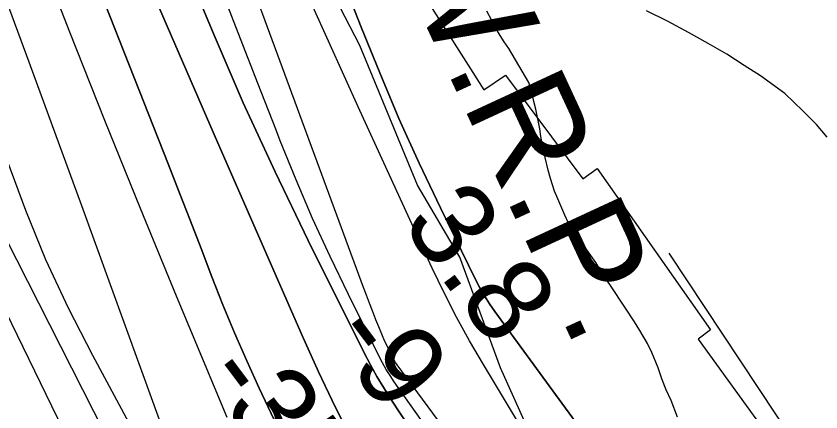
# Model space of a CAD drawing. Extents: x 3567028 to 3605064, y 510945 to 536587.
# Drawn here: x 3579101 to 3579738, y 530496 to 530809 of the extents above; entities that cross this region are included whole.
import ezdxf

# ---------------------------------------------------------------- set-up
doc = ezdxf.new("R2010")
doc.units = 0
for name, color, linetype in [('V-RIVR-EDGE', 7, 'Continuous'), ('V-RIVR-RANG', 7, 'Continuous'), ('V-RRAP-FSHR', 7, 'Continuous'), ('V-RRAP-RVMT', 7, 'Continuous'), ('V-SITE-VEGE', 7, 'Continuous'), ('V-TOPO-DPTH', 7, 'Continuous'), ('V-TOPO-MAJR', 7, 'Continuous'), ('V-TOPO-MINR', 7, 'Continuous'), ('V-TOPO-WATR', 7, 'Continuous'), ('V-TOPO-WATR-IDEN', 7, 'Continuous'), ('V-WETL-SWMP', 7, 'Continuous')]:
    doc.layers.add(name, color=color, linetype=linetype)

msp = doc.modelspace()

# ---------------------------------------------------------------- linework, layer by layer
at = {"layer": 'V-RIVR-EDGE'}
msp.add_lwpolyline([(3579514.72, 530462.65), (3579484.25, 530530.74), (3579451.99, 530618.44), (3579418.43, 530675.5), (3579372.75, 530785.91), (3579337.99, 530853.39), (3579300.26, 530958.26), (3579257.55, 531030.06), (3579223.39, 531093.25), (3579207.54, 531126.38), (3579192.44, 531212.2), (3579171.12, 531262.49)], dxfattribs=at)
at = {"layer": 'V-RRAP-FSHR'}
msp.add_lwpolyline([(3579617.49, 530621.66), (3579815.21, 530322.96), (3579894.56, 530194.06), (3579936.47, 530070.35), (3579998.06, 529936.51), (3580089.68, 529839.06), (3580197.58, 529749.51), (3580318.38, 529667.87), (3580467.84, 529591.15), (3580544.57, 529572.68), (3580671.85, 529512.09)], dxfattribs=at)
at = {"layer": 'V-RRAP-RVMT'}
for p, q in [((3579389.55, 530879.64), (3579470.85, 530750.98)), ((3579470.85, 530750.98), (3579488.26, 530762.49)), ((3579488.26, 530762.49), (3579549.35, 530680.51)), ((3579549.35, 530680.51), (3579560.62, 530688.63)), ((3579560.62, 530688.63), (3579650.29, 530561)), ((3579650.29, 530561), (3579640.58, 530553.51)), ((3579640.58, 530553.51), (3579812.75, 530316.3))]:
    msp.add_line(p, q, dxfattribs=at)
at = {"layer": 'V-SITE-VEGE'}
for points in [[(3579603.87, 530542.87), (3579600.56, 530550.07), (3579594.56, 530560.27), (3579590.35, 530567.16), (3579583.14, 530577.96), (3579570.83, 530596.84), (3579566.02, 530603.44), (3579559.72, 530614.23), (3579548.61, 530629.83), (3579544.4, 530635.22), (3579541.1, 530640.32), (3579538.1, 530645.42), (3579535.09, 530651.71), (3579529.68, 530664.61), (3579526.98, 530670.61), (3579523.67, 530680.8), (3579521.87, 530687.4), (3579519.46, 530697.3), (3579516.15, 530713.8), (3579515.24, 530720.09), (3579512.23, 530735.69), (3579510.43, 530741.69), (3579509.22, 530747.99), (3579506.52, 530756.69), (3579490.9, 530783.67), (3579486.99, 530788.77), (3579483.99, 530793.87), (3579479.79, 530801.06), (3579477.38, 530805.86), (3579473.48, 530813.06)], [(3579624.3, 530491.89), (3579619.19, 530505.09), (3579615.29, 530513.48), (3579611.98, 530522.18), (3579608.98, 530530.88), (3579603.87, 530542.87)]]:
    msp.add_lwpolyline(points, dxfattribs=at)
at = {"layer": 'V-TOPO-DPTH'}
for points in [[(3578940.6, 531474), (3579080.39, 531133.25), (3579124.43, 531026.96), (3579168.98, 530920.88), (3579214.27, 530815.11), (3579260.06, 530709.56), (3579327.19, 530556.31), (3579340.16, 530527.72), (3579353.64, 530499.38), (3579367.87, 530471.4)], [(3579367.87, 530471.4), (3579353.64, 530499.38), (3579340.16, 530527.72), (3579327.19, 530556.31), (3579260.06, 530709.56), (3579214.27, 530815.11), (3579168.98, 530920.88), (3579124.43, 531026.96), (3579080.39, 531133.25), (3578940.6, 531474)], [(3578992.11, 531277.63), (3579028.9, 531182.55), (3579065.83, 531087.53), (3579102.95, 530992.58), (3579140.21, 530897.69), (3579221.09, 530692.31), (3579229.84, 530669.99), (3579238.53, 530647.64), (3579247.15, 530625.27), (3579255.71, 530602.88), (3579264.49, 530580.58), (3579273.62, 530558.42), (3579283.27, 530536.49), (3579293.27, 530514.71), (3579309.84, 530479.69)], [(3579309.84, 530479.69), (3579293.27, 530514.71), (3579283.27, 530536.49), (3579273.62, 530558.42), (3579264.49, 530580.58), (3579255.71, 530602.88), (3579247.15, 530625.27), (3579238.53, 530647.64), (3579229.84, 530669.99), (3579221.09, 530692.31), (3579140.21, 530897.69), (3579102.95, 530992.58), (3579065.83, 531087.53), (3579028.9, 531182.55), (3578992.11, 531277.63)], [(3579065.09, 531280.58), (3579085.51, 531226.33), (3579106.38, 531172.25), (3579114.68, 531151.14), (3579140.1, 531086.66), (3579165.6, 531022.2), (3579191.2, 530957.78), (3579216.87, 530893.4), (3579233.61, 530851.52), (3579256.66, 530795.85), (3579280.6, 530740.58), (3579305.87, 530685.91), (3579332.05, 530631.64), (3579376.3, 530542.67), (3579381.18, 530533.28), (3579386.29, 530524.02), (3579391.73, 530514.94), (3579397.4, 530506), (3579536.06, 530295.52)], [(3579536.06, 530295.52), (3579397.4, 530506), (3579391.73, 530514.94), (3579386.29, 530524.02), (3579381.18, 530533.28), (3579376.3, 530542.67), (3579332.05, 530631.64), (3579305.87, 530685.91), (3579280.6, 530740.58), (3579256.66, 530795.85), (3579233.61, 530851.52), (3579216.87, 530893.4), (3579191.2, 530957.78), (3579165.6, 531022.2), (3579140.1, 531086.66), (3579114.68, 531151.14), (3579106.38, 531172.25), (3579085.51, 531226.33), (3579065.09, 531280.58)], [(3579687, 530147.53), (3579402.26, 530533.32), (3579401.04, 530535.13), (3579400.5, 530536.07), (3579399.99, 530537.04), (3579395.42, 530546.21), (3579392.74, 530551.81), (3579390.16, 530557.46), (3579387.74, 530563.18), (3579385.43, 530568.95), (3579385.15, 530569.69), (3579382.79, 530575.87), (3579380.45, 530582.06), (3579378.13, 530588.25), (3579375.82, 530594.45), (3579296.01, 530810.55), (3579253.3, 530924.6), (3579209.9, 531038.39), (3579165.47, 531151.78), (3579120.36, 531264.91)], [(3579201.22, 531060.56), (3579304.06, 531077.63), (3579319.05, 530991.49), (3579328.34, 530946.24), (3579339.4, 530901.48), (3579353.13, 530857.46), (3579368.63, 530813.94), (3579373.93, 530800.38), (3579388.57, 530764.21), (3579403.8, 530728.3), (3579419.91, 530692.77), (3579436.61, 530657.51), (3579464.35, 530600.73), (3579467.79, 530594.15), (3579471.45, 530587.7), (3579475.44, 530581.46), (3579479.67, 530575.35), (3579652.43, 530339.15), (3579715.16, 530252.46), (3580119.56, 529641.64), (3580133.37, 529627.98), (3580148.41, 529615.41), (3580300.66, 529503.78)], [(3579687, 530147.53), (3579402.26, 530533.32), (3579401.04, 530535.13), (3579400.5, 530536.07), (3579399.99, 530537.04), (3579395.42, 530546.21), (3579392.74, 530551.81), (3579390.16, 530557.46), (3579387.74, 530563.18), (3579385.43, 530568.95), (3579385.15, 530569.69), (3579382.79, 530575.87), (3579380.45, 530582.06), (3579378.13, 530588.25), (3579375.82, 530594.45), (3579296.01, 530810.55), (3579253.3, 530924.6), (3579209.9, 531038.39), (3579201.22, 531060.56)]]:
    msp.add_lwpolyline(points, dxfattribs=at)
at = {"layer": 'V-TOPO-MAJR'}
msp.add_lwpolyline([(3579267.89, 530491.46), (3579227.8, 530587.52), (3579199.18, 530656.97), (3579170.97, 530726.58), (3579143.37, 530796.44), (3579116.18, 530866.47), (3579108.55, 530886.38), (3579085.18, 530947.06), (3579061.68, 531007.68), (3579037.96, 531068.23), (3579014.11, 531128.72), (3579006.56, 531147.78), (3578986.64, 531198.79), (3578967.04, 531249.93)], dxfattribs=at)
at = {"layer": 'V-TOPO-MINR'}
for points in [[(3579507.26, 530472.93), (3579470.59, 530533.48), (3579459.73, 530552.12), (3579449.31, 530570.99), (3579439.54, 530590.21), (3579430.21, 530609.66), (3579372.86, 530734.61), (3579335.5, 530816.85), (3579298.54, 530899.27), (3579262.2, 530981.96), (3579226.28, 531064.84), (3579032.35, 531516.86)], [(3579367.87, 530471.4), (3579353.64, 530499.38), (3579340.16, 530527.72), (3579327.19, 530556.31), (3579260.06, 530709.56), (3579214.27, 530815.11), (3579168.98, 530920.88), (3579124.43, 531026.96), (3579080.39, 531133.25), (3578940.6, 531474)], [(3579226.02, 530420.27), (3579161.38, 530540.47), (3579142.26, 530578.17), (3579124.39, 530616.42), (3579108.39, 530655.48), (3579093.63, 530695.1), (3579079.84, 530735.13), (3579066.1, 530775.18), (3579052.41, 530815.25), (3579038.76, 530855.33), (3579019.8, 530911.17), (3578996.38, 530979.06), (3578972.52, 531046.8), (3578948.02, 531114.31), (3578923.07, 531181.66), (3578838.57, 531406.51)], [(3579234.93, 530432.94), (3579151.7, 530661.85), (3579109.14, 530777.81), (3579066.14, 530893.61), (3579022.44, 531009.14), (3578978.29, 531124.51), (3578886.88, 531361.27)], [(3579526.82, 529024.01), (3579205.85, 530349.07), (3579190.25, 530377.28), (3579175.34, 530405.86), (3579160.89, 530434.69), (3578960.62, 530846.75), (3578925.79, 530923.6), (3578893.79, 531001.53), (3578866.03, 531081.06), (3578841.09, 531161.67), (3578799.2, 531311.24)], [(3579309.84, 530479.69), (3579293.27, 530514.71), (3579283.27, 530536.49), (3579273.62, 530558.42), (3579264.49, 530580.58), (3579255.71, 530602.88), (3579247.15, 530625.27), (3579238.53, 530647.64), (3579229.84, 530669.99), (3579221.09, 530692.31), (3579140.21, 530897.69), (3579102.95, 530992.58), (3579065.83, 531087.53), (3579028.9, 531182.55), (3578992.11, 531277.63)], [(3579536.06, 530295.52), (3579397.4, 530506), (3579391.73, 530514.94), (3579386.29, 530524.02), (3579381.18, 530533.28), (3579376.3, 530542.67), (3579332.05, 530631.64), (3579305.87, 530685.91), (3579280.6, 530740.58), (3579256.66, 530795.85), (3579233.61, 530851.52), (3579216.87, 530893.4), (3579191.2, 530957.78), (3579165.6, 531022.2), (3579140.1, 531086.66), (3579114.68, 531151.14), (3579106.38, 531172.25), (3579085.51, 531226.33), (3579065.09, 531280.58)], [(3579197.38, 530427.14), (3579065.85, 530685.44), (3579036.5, 530746.84), (3579009.24, 530809.09), (3578985.13, 530872.62), (3578963.11, 530937.01), (3578942.97, 531001.09), (3578932.61, 531034.09), (3578922.23, 531067.08), (3578911.86, 531100.08), (3578901.48, 531133.07), (3578890.89, 531165.99), (3578879.99, 531198.81), (3578868.66, 531231.47), (3578857.03, 531264.04)], [(3579687, 530147.53), (3579402.26, 530533.32), (3579401.04, 530535.13), (3579400.5, 530536.07), (3579399.99, 530537.04), (3579395.42, 530546.21), (3579392.74, 530551.81), (3579390.16, 530557.46), (3579387.74, 530563.18), (3579385.43, 530568.95), (3579385.15, 530569.69), (3579382.79, 530575.87), (3579380.45, 530582.06), (3579378.13, 530588.25), (3579375.82, 530594.45), (3579296.01, 530810.55), (3579253.3, 530924.6), (3579209.9, 531038.39), (3579165.47, 531151.78), (3579120.36, 531264.91)], [(3579610.02, 530223.16), (3579400.1, 530519.85), (3579396.84, 530524.69), (3579393.73, 530529.62), (3579390.86, 530534.69), (3579388.14, 530539.86), (3579363.73, 530588.93), (3579349.33, 530618.88), (3579335.46, 530649.06), (3579322.4, 530679.61), (3579309.88, 530710.39), (3579306.21, 530719.76), (3579292.3, 530755.43), (3579278.46, 530791.12), (3579264.71, 530826.85), (3579251.02, 530862.6), (3579204.03, 530985.86), (3579170.92, 531072.74), (3579137.85, 531159.64), (3579104.83, 531246.55)]]:
    msp.add_lwpolyline(points, dxfattribs=at)
at = {"layer": 'V-TOPO-WATR'}
msp.add_lwpolyline([(3580300.66, 529503.78), (3580148.41, 529615.41), (3580133.37, 529627.98), (3580119.56, 529641.64), (3579715.16, 530252.46), (3579652.43, 530339.15), (3579479.67, 530575.35), (3579475.44, 530581.46), (3579471.45, 530587.7), (3579467.79, 530594.15), (3579464.35, 530600.73), (3579436.61, 530657.51), (3579419.91, 530692.77), (3579403.8, 530728.3), (3579388.57, 530764.21), (3579373.93, 530800.38), (3579368.63, 530813.94), (3579353.13, 530857.46), (3579339.4, 530901.48), (3579328.34, 530946.24), (3579319.05, 530991.49), (3579304.06, 531077.63)], dxfattribs=at)
at = {"layer": 'V-WETL-SWMP'}
for p, q in [((3579616.37, 530805.15), (3579599.85, 530813.52)), ((3579633.02, 530796.12), (3579616.37, 530805.15)), ((3579648.62, 530787.61), (3579633.02, 530796.12)), ((3579663.43, 530778.97), (3579648.62, 530787.61)), ((3579676.93, 530770.07), (3579663.43, 530778.97)), ((3579690.05, 530761.83), (3579676.93, 530770.07)), ((3579709.19, 530748.08), (3579690.05, 530761.83)), ((3579723.62, 530734.34), (3579709.19, 530748.08)), ((3579734.37, 530723.47), (3579723.62, 530734.34)), ((3579742.77, 530713.52), (3579734.37, 530723.47))]:
    msp.add_line(p, q, dxfattribs=at)

# ---------------------------------------------------------------- texts
at = {"layer": 'V-RIVR-RANG'}
for s, rotation, p in [('3.8', 306.63833, (3579404.92, 530644.85)), ('-9', 306.92631, (3579346.46, 530555.48)), ('-35', 306.92631, (3579245.61, 530523.22))]:
    msp.add_text(s, height=67, rotation=rotation, dxfattribs=at).set_placement(p)
at = {"layer": 'V-TOPO-WATR-IDEN'}
msp.add_text('L.W.R.P.', height=83, rotation=294.86546, dxfattribs=at).set_placement((3579357.68, 530947.08))

doc.saveas('drawing.dxf')
